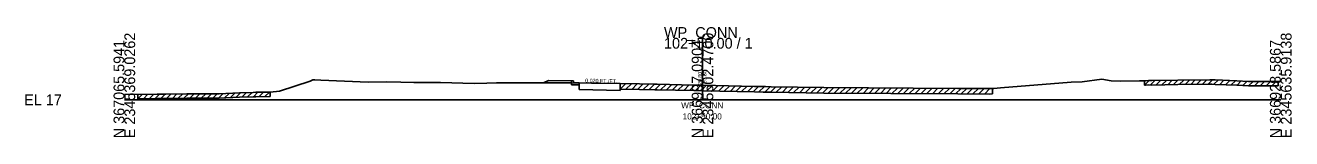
# Model space of a CAD drawing. Extents: x -26 to 2345577, y -10 to 367097.
# Drawn here: x -25.7 to 302.8, y 1990.3 to 2019 of the extents above; entities that cross this region are included whole.
import ezdxf

# ---------------------------------------------------------------- set-up
doc = ezdxf.new("R2010")
doc.units = 0
for name, color, linetype in [('RD_GPK_XS_Cell', 7, 'Continuous'), ('RD_XS_Base', 7, 'Continuous'), ('RD_XS_CurbTop', 7, 'Continuous'), ('RD_XS_EarthShd', 7, 'Continuous'), ('RD_XS_ExGround', 7, 'Continuous'), ('RD_XS_ExPaveRet', 7, 'Continuous'), ('RD_XS_Pave', 7, 'Continuous'), ('RD_XS_TieSlope', 7, 'Continuous'), ('RD_XS_TX_Elev_EX', 7, 'Continuous'), ('RD_XS_TX_Elev_PR', 7, 'Continuous'), ('RD_XS_TX_Slope', 7, 'Continuous'), ('RD_XS_TX_Station', 7, 'Continuous'), ('RD_XS_TX_TOC', 7, 'Continuous')]:
    doc.layers.add(name, color=color, linetype=linetype)

msp = doc.modelspace()

# ---------------------------------------------------------------- linework, layer by layer
at = {"layer": 'RD_GPK_XS_Cell'}
for p, q in [((150, 2000), (150, 2016.13)), ((0, 2000), (150, 2000)), ((150, 2000), (300, 2000))]:
    msp.add_line(p, q, dxfattribs=at)
at = {"layer": 'RD_XS_Base'}
for p, q in [((116, 2004.93), (116, 2003.93)), ((118, 2003.9), (118, 2004.41)), ((128.62, 2002.44), (128.64, 2004.21)), ((116, 2003.93), (116.5, 2003.93)), ((116.5, 2003.93), (118, 2003.9)), ((118, 2002.65), (118, 2003.93)), ((118, 2002.65), (128.62, 2002.44))]:
    msp.add_line(p, q, dxfattribs=at)
at = {"layer": 'RD_XS_CurbTop'}
for p, q in [((116.5, 2004.93), (116, 2004.93)), ((116.58, 2004.43), (116.5, 2004.93)), ((118, 2004.41), (116.58, 2004.43)), ((118, 2004.43), (118, 2004.41))]:
    msp.add_line(p, q, dxfattribs=at)
at = {"layer": 'RD_XS_EarthShd'}
msp.add_line((116, 2004.93), (110, 2005.05), dxfattribs=at)
at = {"layer": 'RD_XS_ExGround'}
msp.add_lwpolyline([(0, 2001.36), (8.47, 2001.46), (10.21, 2001.48), (10.75, 2001.49), (16.19, 2001.6), (18.93, 2001.58), (24.6, 2001.57), (29.86, 2001.8), (33.4, 2001.95), (34.12, 2001.96), (37.87, 2002.03), (40.25, 2002.24), (48.23, 2004.87), (48.91, 2005.21), (49.45, 2005.17), (50.94, 2005.11), (63.24, 2004.6), (67.93, 2004.65), (71.75, 2004.57), (75.08, 2004.5), (82.06, 2004.49), (90.72, 2004.28), (94.04, 2004.32), (96.58, 2004.45), (103.37, 2004.44), (105.29, 2004.45), (107.41, 2004.41), (116.01, 2004.39), (121.23, 2004.36), (128.63, 2004.21), (133.61, 2004.13), (137.63, 2004.06), (138.2, 2004.05), (147.74, 2003.85), (150, 2003.8), (163.49, 2003.5), (165.7, 2003.45), (166.37, 2003.44), (167.79, 2003.42), (181.48, 2003.19), (216.19, 2002.98), (224.55, 2002.94), (225.58, 2002.99), (227.26, 2003.14), (245.66, 2004.63), (248.46, 2004.68), (253.57, 2005.38), (256.01, 2004.97), (258.45, 2004.9), (263.35, 2004.91), (264.96, 2004.98), (265.73, 2005.02), (266.59, 2004.99), (273.28, 2005.12), (281.6, 2005.22), (282.09, 2005.23), (283.01, 2005.17), (288.57, 2004.97), (291.63, 2004.8), (295.6, 2004.76), (300, 2004.74)], dxfattribs=at)
at = {"layer": 'RD_XS_ExPaveRet'}
for p, q in [((128.63, 2002.7), (128.63, 2004.21)), ((128.63, 2002.78), (130.05, 2004.19)), ((130.13, 2002.75), (131.55, 2004.16)), ((131.63, 2002.73), (133.05, 2004.14)), ((133.13, 2002.7), (134.55, 2004.11)), ((134.63, 2002.68), (136.05, 2004.09)), ((136.13, 2002.65), (137.55, 2004.07)), ((264.68, 2003.83), (265.87, 2005.02)), ((264.68, 2003.83), (264.68, 2004.97)), ((266.18, 2003.87), (267.32, 2005.01)), ((267.68, 2003.87), (268.84, 2005.04)), ((269.18, 2003.9), (270.34, 2005.06)), ((270.68, 2003.93), (271.84, 2005.09)), ((272.18, 2003.95), (273.34, 2005.12)), ((273.28, 2003.97), (281.6, 2004.07)), ((273.68, 2003.98), (274.83, 2005.14)), ((275.18, 2004), (276.33, 2005.15)), ((276.68, 2004.01), (277.83, 2005.17)), ((278.18, 2004.03), (279.33, 2005.19)), ((279.68, 2004.05), (280.83, 2005.21)), ((281.18, 2004.07), (282.32, 2005.21)), ((281.6, 2004.07), (282.09, 2004.09)), ((282.09, 2004.09), (283.01, 2004.03)), ((282.68, 2004.05), (283.77, 2005.14)), ((284.18, 2003.99), (285.28, 2005.09)), ((285.68, 2003.93), (286.78, 2005.04)), ((287.18, 2003.88), (288.28, 2004.98)), ((288.68, 2003.83), (289.76, 2004.91)), ((290.18, 2003.74), (291.26, 2004.83)), ((291.68, 2003.66), (292.81, 2004.79)), ((293.18, 2003.64), (294.31, 2004.77)), ((294.68, 2003.63), (295.81, 2004.76)), ((296.18, 2003.61), (297.32, 2004.75)), ((297.68, 2003.61), (298.82, 2004.75)), ((299.35, 2004.75), (299.35, 2003.6)), ((3.46, 2000.25), (4.62, 2001.41)), ((3.46, 2000.25), (3.46, 2001.4)), ((4.96, 2000.27), (6.12, 2001.43)), ((6.46, 2000.29), (7.62, 2001.45)), ((7.96, 2000.31), (9.12, 2001.46)), ((9.46, 2000.33), (10.62, 2001.49)), ((10.96, 2000.35), (12.13, 2001.52)), ((12.46, 2000.38), (13.63, 2001.55)), ((13.96, 2000.41), (15.13, 2001.58)), ((15.46, 2000.44), (16.61, 2001.6)), ((16.96, 2000.45), (18.09, 2001.59)), ((18.46, 2000.44), (19.6, 2001.58)), ((19.96, 2000.43), (21.1, 2001.57)), ((21.46, 2000.43), (22.6, 2001.57)), ((22.96, 2000.43), (24.1, 2001.57)), ((24.46, 2000.42), (25.65, 2001.61)), ((25.96, 2000.48), (27.16, 2001.68)), ((27.46, 2000.55), (28.66, 2001.74)), ((28.96, 2000.61), (30.16, 2001.81)), ((29.86, 2000.65), (33.4, 2000.8)), ((30.46, 2000.68), (31.65, 2001.87)), ((31.96, 2000.74), (33.15, 2001.94)), ((33.4, 2000.8), (34.12, 2000.82)), ((33.46, 2000.81), (34.63, 2001.97)), ((34.12, 2000.82), (37.87, 2000.89)), ((34.96, 2000.83), (36.12, 2002)), ((36.46, 2000.86), (37.62, 2002.02)), ((37.87, 2002.03), (37.87, 2000.89)), ((128.63, 2002.78), (133.61, 2002.69)), ((133.61, 2002.69), (137.63, 2002.63)), ((137.63, 2002.63), (139.04, 2004.03)), ((137.63, 2002.63), (138.2, 2002.61)), ((138.2, 2002.61), (147.74, 2002.41)), ((139.13, 2002.59), (140.54, 2004)), ((140.63, 2002.56), (142.04, 2003.97)), ((142.13, 2002.53), (143.54, 2003.94)), ((143.63, 2002.5), (145.04, 2003.91)), ((145.13, 2002.47), (146.54, 2003.88)), ((146.63, 2002.44), (148.04, 2003.84)), ((147.74, 2002.41), (150, 2002.36)), ((148.13, 2002.41), (149.54, 2003.81)), ((149.63, 2002.37), (151.04, 2003.78)), ((150, 2002.36), (163.49, 2002.07)), ((151.13, 2002.34), (152.54, 2003.74)), ((152.63, 2002.31), (154.04, 2003.71)), ((154.13, 2002.27), (155.54, 2003.68)), ((155.63, 2002.24), (157.04, 2003.65)), ((157.13, 2002.21), (158.54, 2003.61)), ((158.63, 2002.17), (160.04, 2003.58)), ((160.13, 2002.14), (161.54, 2003.55)), ((161.63, 2002.11), (163.04, 2003.51)), ((163.13, 2002.07), (164.54, 2003.48)), ((163.49, 2002.07), (165.7, 2002.02)), ((164.63, 2002.04), (166.04, 2003.45)), ((165.7, 2002.02), (166.37, 2002.01)), ((166.13, 2002.01), (167.55, 2003.42)), ((166.37, 2002.01), (167.79, 2001.98)), ((167.63, 2001.98), (169.05, 2003.4)), ((167.79, 2001.98), (181.48, 2001.75)), ((169.13, 2001.96), (170.55, 2003.37)), ((170.63, 2001.93), (172.05, 2003.35)), ((172.13, 2001.91), (173.55, 2003.32)), ((173.63, 2001.88), (175.05, 2003.29)), ((175.13, 2001.86), (176.55, 2003.27)), ((176.63, 2001.83), (178.05, 2003.24)), ((178.13, 2001.81), (179.55, 2003.22)), ((179.63, 2001.78), (181.05, 2003.19)), ((181.13, 2001.76), (182.56, 2003.18)), ((181.48, 2001.75), (216.19, 2001.54)), ((182.63, 2001.74), (184.06, 2003.17)), ((184.13, 2001.73), (185.56, 2003.16)), ((185.63, 2001.73), (187.06, 2003.15)), ((187.13, 2001.72), (188.56, 2003.14)), ((188.63, 2001.71), (190.06, 2003.14)), ((190.13, 2001.7), (191.56, 2003.13)), ((191.63, 2001.69), (193.06, 2003.12)), ((193.13, 2001.68), (194.56, 2003.11)), ((194.63, 2001.67), (196.06, 2003.1)), ((196.13, 2001.66), (197.56, 2003.09)), ((197.63, 2001.65), (199.06, 2003.08)), ((199.13, 2001.64), (200.56, 2003.07)), ((200.63, 2001.63), (202.06, 2003.06)), ((202.13, 2001.63), (203.56, 2003.05)), ((203.63, 2001.62), (205.06, 2003.04)), ((205.13, 2001.61), (206.56, 2003.04)), ((206.63, 2001.6), (208.06, 2003.03)), ((208.13, 2001.59), (209.56, 2003.02)), ((209.63, 2001.58), (211.06, 2003.01)), ((211.13, 2001.57), (212.56, 2003)), ((212.63, 2001.56), (214.06, 2002.99)), ((214.13, 2001.55), (215.56, 2002.98)), ((215.63, 2001.54), (217.06, 2002.97)), ((216.19, 2001.54), (224.55, 2001.5)), ((217.13, 2001.54), (218.56, 2002.97)), ((218.63, 2001.53), (220.06, 2002.96)), ((220.13, 2001.52), (221.56, 2002.95)), ((221.63, 2001.51), (223.06, 2002.94)), ((223.13, 2001.51), (224.57, 2002.94)), ((224.55, 2001.5), (225.25, 2001.53)), ((225.25, 2002.97), (225.25, 2001.53)), ((264.68, 2003.83), (264.96, 2003.84)), ((264.96, 2003.84), (265.73, 2003.88)), ((265.73, 2003.88), (266.59, 2003.85)), ((266.59, 2003.85), (273.28, 2003.97)), ((283.01, 2004.03), (288.57, 2003.83)), ((288.57, 2003.83), (291.63, 2003.66)), ((291.63, 2003.66), (295.6, 2003.61)), ((295.6, 2003.61), (299.35, 2003.6)), ((3.46, 2000.25), (8.47, 2000.31)), ((8.47, 2000.31), (10.21, 2000.34)), ((10.21, 2000.34), (10.75, 2000.35)), ((10.75, 2000.35), (16.19, 2000.46)), ((16.19, 2000.46), (18.93, 2000.44)), ((18.93, 2000.44), (24.6, 2000.42)), ((24.6, 2000.42), (29.86, 2000.65))]:
    msp.add_line(p, q, dxfattribs=at)
at = {"layer": 'RD_XS_Pave'}
msp.add_line((118, 2004.43), (128.63, 2004.21), dxfattribs=at)
at = {"layer": 'RD_XS_TieSlope'}
msp.add_line((110, 2005.05), (108.71, 2004.41), dxfattribs=at)

# ---------------------------------------------------------------- texts
at = {"layer": 'RD_GPK_XS_Cell'}
for s, p in [('E 2345369.0262', (2.8, 1990)), ('E 2345502.4700', (152.8, 1990)), ('E 2345635.9138', (302.8, 1990)), ('N 367065.5941', (0, 1990)), ('N 366997.0904', (150, 1990)), ('N 366928.5867', (300, 1990))]:
    msp.add_text(s, height=2.8, rotation=90, dxfattribs=at).set_placement(p)
for s, p in [('WP_CONN', (140, 2016.13)), ('102+50.00 / 1', (140, 2013.33)), ('EL 17', (-26, 1998.6))]:
    msp.add_text(s, height=2.8, dxfattribs=at).set_placement(p)
at = {"layer": 'RD_XS_TX_Elev_EX'}
msp.add_text('20.80', height=1, rotation=90, dxfattribs=at).set_placement((149.82, 2003.84))
at = {"layer": 'RD_XS_TX_Elev_PR'}
msp.add_text(' 20.80', height=1, rotation=90, dxfattribs=at).set_placement((151, 2003.86))
at = {"layer": 'RD_XS_TX_Slope'}
msp.add_text('0.020 FT./FT.', height=1, rotation=358.8542, dxfattribs=at).set_placement((119.55, 2004.52))
at = {"layer": 'RD_XS_TX_Station'}
for s, p in [('WP_CONN', (144.45, 1997.78)), ('102+50.00', (144.83, 1994.88))]:
    msp.add_text(s, height=1.6, dxfattribs=at).set_placement(p)
at = {"layer": 'RD_XS_TX_TOC'}
msp.add_text('TOCLT', height=0.05, dxfattribs=at).set_placement((116.55, 2004.88))

doc.saveas('drawing.dxf')
